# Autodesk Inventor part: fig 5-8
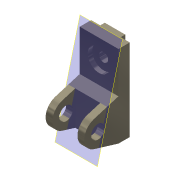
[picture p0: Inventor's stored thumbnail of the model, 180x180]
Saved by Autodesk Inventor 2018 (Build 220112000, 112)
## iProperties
Shininess: 65.0
Angle Display Precision: 2
Document Length Units: 11269
Document Angle Units: 11279
Document Time Units: 11290
Document Mass Units: 11283
Document Length Units Precision: 3
Document Angle Units Precision: 2
Compacted: False
Created: 2001-11
Part Number: fig 5-8
Document SubType Name: Modeling
Designer: Renu Muthoo
Density: 1 g/cm^3
Material: Generic
Appearance: Metal-Titanium (Polished)
Density: 0.0
Volumn: 0.0
Area: 0.0
PropertySet Name: Model Information
Control State: 0
Master: False
Checked Out: False
Author: Renu Muthoo
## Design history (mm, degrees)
node "Sketch1"
sketch "Sketch2"
  geometry: L1 (33.257, 104.664)-(33.257, -75.336); L2 (33.257, -75.336)-(8.257, -75.336); L3 (8.257, -75.336)-(-45.451, -59.045); L4 (-45.451, -1.628)-(8.257, 14.664); L5 (8.257, 14.664)-(8.257, 104.664); L6 (8.257, 104.664)-(33.257, 104.664); C1 r 15 at (-36.743, -30.336); A1 r 30 centre (-36.743, -30.336) between (-45.451, -1.628) and (-45.451, -59.045)
  constraints: 12 end point, 2 centre point, 2 equal length, 2 parallel, 2 point on circle, 2 tangent, 1 coincident, 1 perpendicular, 1 vertical
  dimensions: "d0" = 180 distance of L1.start L1.end; "d1" = 30 radius of A1; "d2" = 25 distance of L5.end L1.start; "d3" = 45 distance from line of L2 A1.centre; "d4" = 70 distance from line of L1 A1.centre; "d5" = 30 diameter of C1
extrude "Extrusion1" new body sketch "Sketch2" distance "d6" = 85; taper "d7" = 0 deg
workplane "Work Plane1"
sketch "Sketch3"
  geometry: L1 (15, 62.364)-(70, 62.364); L2 (70, 62.364)-(70, -52.386); L3 (70, -52.386)-(15, -52.386); L4 (15, -52.386)-(15, 62.364); L5 (0, -45)-(0, -28.708) reference
  constraints: 8 end point, 2 parallel, 1 horizontal, 1 perpendicular
  dimensions: "d8" = 55 distance of L1.start L1.end; "d9" = 15 distance between parallel lines of L5 L4
extrude "Extrusion2" cut sketch "Sketch3" distance "d10" = 50; taper "d11" = 0 deg
sketch "Sketch4"
  geometry: L1 (0, 25)-(85, 25) reference; L2 (0, 0)-(0, 25) reference; L3 (20, 25)-(65, 25); L4 (65, 25)-(65, 35); L5 (65, 35)-(20, 35); L6 (20, 35)-(20, 25)
  constraints: 8 end point, 2 parallel, 1 horizontal, 1 perpendicular, 1 point on line
  dimensions: "d12" = 45 distance of L4.end L5.end; "d13" = 10 distance of L3.end L4.end; "d14" = 20 distance between parallel lines of L2 L6
extrude "Extrusion3" join sketch "Sketch4" stored distance "d15" = 50; taper "d16" = 0 deg
sketch "Sketch5"
  geometry: L1 (85, 0)-(85, 90) reference; L2 (0, 90)-(85, 90) reference; 1 further point
  dimensions: "d17" = 42 distance from line of L2 point (42.5, 48); "d18" = 42.5 distance from line of L1 point (42.5, 48)
hole "Hole1" sketch "Sketch5" at (42.5, 48) diameter "d19" = 20; stored, may be unused: countersink angle "d23" = 82 deg, drill point angle "d25" = 118 deg; dims "d20" = 6, "d21" = 50, "d22" = 10, "d24" = 8
workplane "Work Plane5"
body "Solid1"
